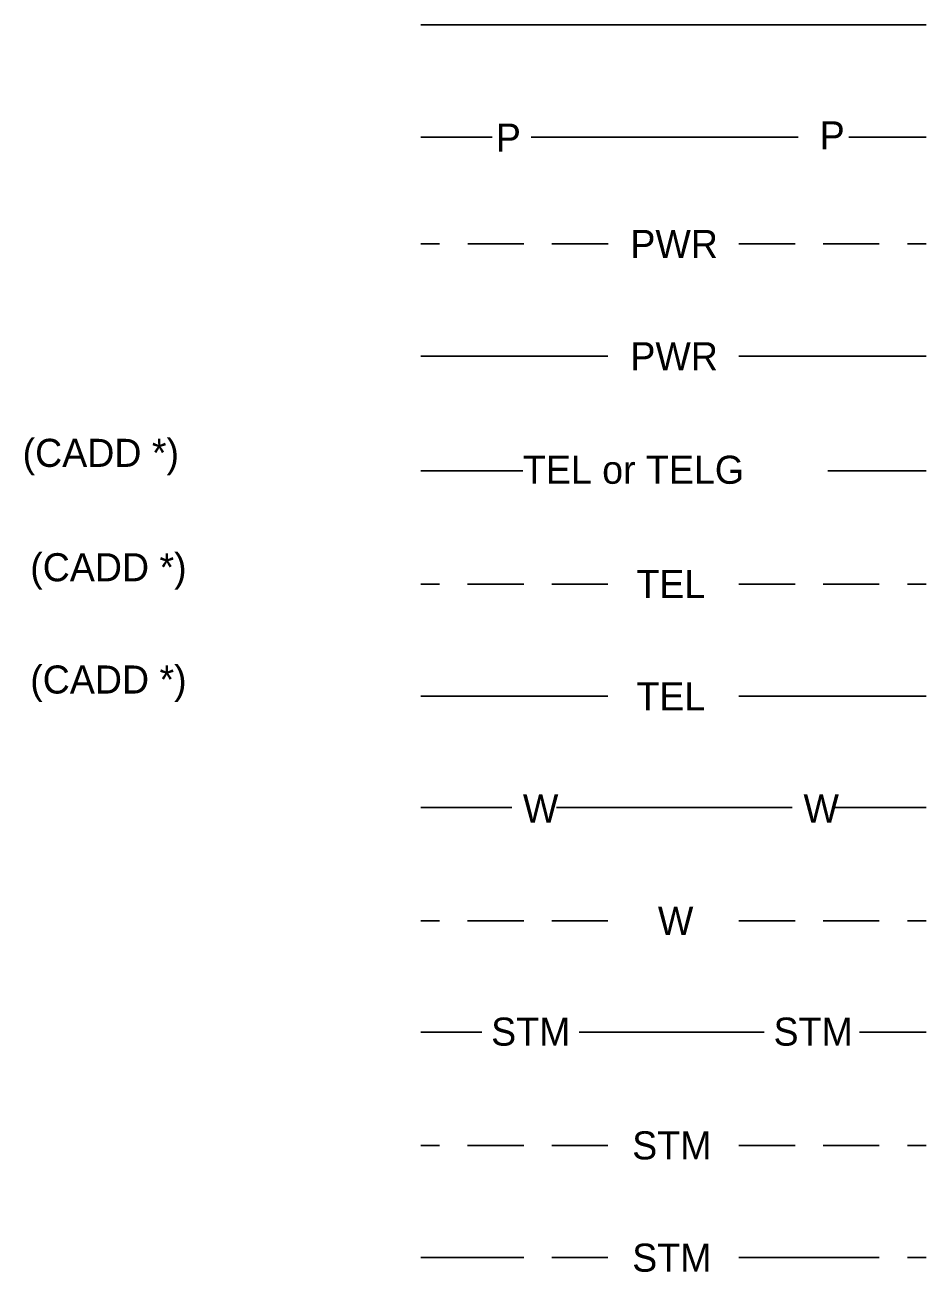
# Model space of a CAD drawing. Extents: x 49991.4 to 50021, y 49987.6 to 50011.4.
# Drawn here: x 50007.447 to 50009.374, y 49990.704 to 49993.37 of the extents above; entities that cross this region are included whole.
import ezdxf

# ---------------------------------------------------------------- set-up
doc = ezdxf.new("R2010")
doc.units = 0
doc.layers.add('Level 1', color=7, linetype='Continuous')
doc.layers.add('Level 2', color=7, linetype='Continuous')

msp = doc.modelspace()

# ---------------------------------------------------------------- linework, layer by layer
at = {"layer": 'Level 1'}
for p, q in [((50008.2935, 49993.3703), (50009.3735, 49993.3703)), ((50008.2935, 49993.1303), (50008.4459, 49993.1303)), ((50008.5292, 49993.1303), (50009.1002, 49993.1303)), ((50009.2086, 49993.1303), (50009.3735, 49993.1303)), ((50008.2935, 49992.9022), (50008.3336, 49992.9022)), ((50008.3936, 49992.9022), (50008.5136, 49992.9022)), ((50008.5736, 49992.9022), (50008.6936, 49992.9022)), ((50008.9736, 49992.9022), (50009.0936, 49992.9022)), ((50009.1536, 49992.9022), (50009.2736, 49992.9022)), ((50009.3336, 49992.9022), (50009.3735, 49992.9022)), ((50008.2935, 49992.6622), (50008.6535, 49992.6622)), ((50008.6535, 49992.6622), (50008.6935, 49992.6622)), ((50008.9735, 49992.6622), (50009.3735, 49992.6622)), ((50008.2935, 49992.4173), (50008.5117, 49992.4173)), ((50009.1635, 49992.4173), (50009.3735, 49992.4173)), ((50008.2935, 49992.1752), (50008.3335, 49992.1752)), ((50008.3935, 49992.1752), (50008.5135, 49992.1752)), ((50008.5735, 49992.1752), (50008.6935, 49992.1752)), ((50008.9735, 49992.1752), (50009.0935, 49992.1752)), ((50009.1535, 49992.1752), (50009.2735, 49992.1752)), ((50009.3335, 49992.1752), (50009.3735, 49992.1752)), ((50008.2935, 49991.9352), (50008.6535, 49991.9352)), ((50008.6535, 49991.9352), (50008.6935, 49991.9352)), ((50008.9735, 49991.9352), (50009.3735, 49991.9352)), ((50008.2935, 49991.6973), (50008.4878, 49991.6973)), ((50008.5837, 49991.6973), (50009.0875, 49991.6973)), ((50009.1794, 49991.6973), (50009.3735, 49991.6973)), ((50008.2935, 49991.4552), (50008.3335, 49991.4552)), ((50008.3935, 49991.4552), (50008.5135, 49991.4552)), ((50008.5735, 49991.4552), (50008.6935, 49991.4552)), ((50008.9735, 49991.4552), (50009.0935, 49991.4552)), ((50009.1535, 49991.4552), (50009.2735, 49991.4552)), ((50009.3335, 49991.4552), (50009.3735, 49991.4552)), ((50008.2935, 49991.2173), (50008.4238, 49991.2173)), ((50008.6317, 49991.2173), (50009.0275, 49991.2173)), ((50009.2314, 49991.2173), (50009.3735, 49991.2173)), ((50008.2935, 49990.9752), (50008.3335, 49990.9752)), ((50008.3935, 49990.9752), (50008.5135, 49990.9752)), ((50008.5735, 49990.9752), (50008.6935, 49990.9752)), ((50008.9735, 49990.9752), (50009.0935, 49990.9752)), ((50009.1535, 49990.9752), (50009.2735, 49990.9752)), ((50009.3335, 49990.9752), (50009.3735, 49990.9752)), ((50008.2935, 49990.7352), (50008.5135, 49990.7352)), ((50008.5735, 49990.7352), (50008.6935, 49990.7352)), ((50008.9735, 49990.7352), (50009.2735, 49990.7352)), ((50009.3335, 49990.7352), (50009.3735, 49990.7352))]:
    msp.add_line(p, q, dxfattribs=at)

# ---------------------------------------------------------------- texts
at = {"layer": 'Level 2'}
for s, height, p in [('P', 0.06, (50008.4539, 49993.0994)), ('P', 0.06, (50009.1461, 49993.1043)), ('PWR', 0.06, (50008.7414, 49992.8722)), ('PWR', 0.06, (50008.7414, 49992.6322)), ('(CADD *)', 0.06, (50007.4422, 49992.4256)), ('TEL or TELG', 0.059999, (50008.5117, 49992.3895)), ('(CADD *)', 0.06, (50007.4585, 49992.1811)), ('TEL', 0.06, (50008.7544, 49992.1452)), ('(CADD *)', 0.06, (50007.4585, 49991.9411)), ('TEL', 0.06, (50008.7544, 49991.9052)), ('W', 0.06, (50008.5117, 49991.6654)), ('W', 0.06, (50009.1115, 49991.6654)), ('W', 0.06, (50008.8003, 49991.4252)), ('STM', 0.06, (50008.4438, 49991.1884)), ('STM', 0.06, (50009.0475, 49991.1884)), ('STM', 0.06, (50008.7453, 49990.9452)), ('STM', 0.06, (50008.7453, 49990.7052))]:
    msp.add_text(s, height=height, dxfattribs=at).set_placement(p)

doc.saveas('drawing.dxf')
